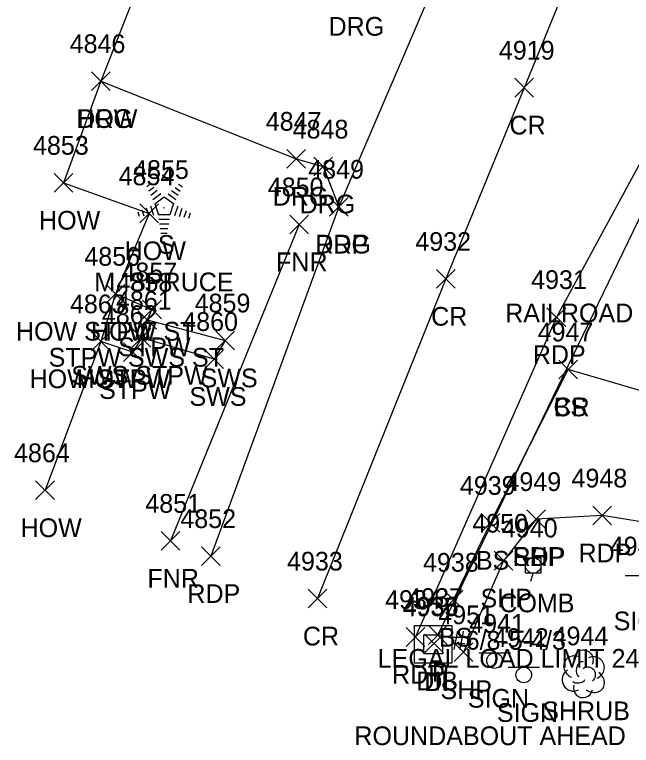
# Model space of a CAD drawing. Extents: x 1653135 to 1655489, y 602711 to 605684.
# Drawn here: x 1653442.7 to 1653508.5, y 604632.5 to 604710.6 of the extents above; entities that cross this region are included whole.
import ezdxf

# ---------------------------------------------------------------- set-up
doc = ezdxf.new("R2010")
doc.units = 0
for name, color, linetype in [('D_A', 7, 'Continuous'), ('D_I', 7, 'Continuous'), ('D_TIC', 7, 'Continuous'), ('DCP', 7, 'Continuous'), ('DS', 7, 'Continuous'), ('L_A', 7, 'Continuous'), ('L_C', 7, 'Continuous'), ('L_I', 7, 'Continuous'), ('L_TIC', 7, 'Continuous'), ('LBC', 7, 'Continuous'), ('LBF', 7, 'Continuous'), ('LELB', 7, 'Continuous'), ('LFNC', 7, 'Continuous'), ('LSH', 7, 'Continuous'), ('LTC', 7, 'Continuous'), ('M_C', 7, 'Continuous'), ('P_A', 7, 'Continuous'), ('P_I', 7, 'Continuous'), ('P_TIC', 7, 'Continuous'), ('PET', 7, 'Continuous'), ('PRC', 7, 'Continuous'), ('PSP', 7, 'Continuous'), ('R_A', 7, 'Continuous'), ('R_I', 7, 'Continuous'), ('R_TIC', 7, 'Continuous'), ('RDG', 7, 'Continuous'), ('RSW', 7, 'Continuous'), ('S_A', 7, 'Continuous'), ('S_C', 7, 'Continuous'), ('S_I', 7, 'Continuous'), ('SSGN', 7, 'Continuous'), ('U_A', 7, 'Continuous'), ('U_C', 7, 'Continuous'), ('U_I', 7, 'Continuous'), ('UP', 7, 'Continuous')]:
    doc.layers.add(name, color=color, linetype=linetype)

msp = doc.modelspace()

# ---------------------------------------------------------------- linework, layer by layer
at = {"layer": 'D_TIC'}
for points in [[(1653486.856, 604643.339), (1653488.856, 604645.339)], [(1653488.856, 604643.339), (1653486.856, 604645.339)], [(1653486.856, 604643.339), (1653488.856, 604645.339)], [(1653488.856, 604643.339), (1653486.856, 604645.339)], [(1653486.449, 604642.424), (1653488.449, 604644.424)], [(1653488.449, 604642.424), (1653486.449, 604644.424)], [(1653486.449, 604642.424), (1653488.449, 604644.424)], [(1653488.449, 604642.424), (1653486.449, 604644.424)]]:
    msp.add_lwpolyline(points, dxfattribs=at)
at = {"layer": 'DCP'}
msp.add_lwpolyline([(1653550.926, 604774.784), (1653487.856, 604644.339)], dxfattribs=at)
at = {"layer": 'DS'}
for p, q in [((1653485.358, 604645.338), (1653489.358, 604645.338)), ((1653485.358, 604641.338), (1653485.358, 604645.338)), ((1653489.358, 604645.338), (1653489.358, 604641.338)), ((1653486.358, 604642.338), (1653486.358, 604644.338)), ((1653486.358, 604644.338), (1653488.358, 604644.338)), ((1653488.358, 604644.338), (1653488.358, 604642.338)), ((1653487.363, 604643.34), (1653487.363, 604643.34)), ((1653487.363, 604643.34), (1653487.363, 604643.34)), ((1653488.358, 604642.338), (1653486.358, 604642.338)), ((1653489.358, 604641.338), (1653485.358, 604641.338))]:
    msp.add_line(p, q, dxfattribs=at)
at = {"layer": 'L_TIC'}
for points in [[(1653450.866, 604702.506), (1653452.866, 604704.506)], [(1653452.866, 604702.506), (1653450.866, 604704.506)], [(1653450.866, 604702.506), (1653452.866, 604704.506)], [(1653452.866, 604702.506), (1653450.866, 604704.506)], [(1653446.898, 604691.645), (1653448.898, 604693.645)], [(1653448.898, 604691.645), (1653446.898, 604693.645)], [(1653446.898, 604691.645), (1653448.898, 604693.645)], [(1653448.898, 604691.645), (1653446.898, 604693.645)], [(1653456.038, 604688.383), (1653458.038, 604690.383)], [(1653458.038, 604688.383), (1653456.038, 604690.383)], [(1653456.038, 604688.383), (1653458.038, 604690.383)], [(1653458.038, 604688.383), (1653456.038, 604690.383)], [(1653472.053, 604687.202), (1653474.053, 604689.202)], [(1653474.053, 604687.202), (1653472.053, 604689.202)], [(1653472.053, 604687.202), (1653474.053, 604689.202)], [(1653474.053, 604687.202), (1653472.053, 604689.202)], [(1653452.437, 604679.785), (1653454.437, 604681.785)], [(1653454.437, 604679.785), (1653452.437, 604681.785)], [(1653452.437, 604679.785), (1653454.437, 604681.785)], [(1653454.437, 604679.785), (1653452.437, 604681.785)], [(1653452.437, 604679.785), (1653454.437, 604681.785)], [(1653454.437, 604679.785), (1653452.437, 604681.785)], [(1653452.437, 604679.785), (1653454.437, 604681.785)], [(1653454.437, 604679.785), (1653452.437, 604681.785)], [(1653456.34, 604678.12), (1653458.34, 604680.12)], [(1653458.34, 604678.12), (1653456.34, 604680.12)], [(1653456.34, 604678.12), (1653458.34, 604680.12)], [(1653458.34, 604678.12), (1653456.34, 604680.12)], [(1653455.818, 604677.007), (1653457.818, 604679.007)], [(1653457.818, 604677.007), (1653455.818, 604679.007)], [(1653455.818, 604677.007), (1653457.818, 604679.007)], [(1653457.818, 604677.007), (1653455.818, 604679.007)], [(1653450.891, 604674.708), (1653452.891, 604676.708)], [(1653452.891, 604674.708), (1653450.891, 604676.708)], [(1653450.891, 604674.708), (1653452.891, 604676.708)], [(1653452.891, 604674.708), (1653450.891, 604676.708)], [(1653450.891, 604674.708), (1653452.891, 604676.708)], [(1653452.891, 604674.708), (1653450.891, 604676.708)], [(1653450.891, 604674.708), (1653452.891, 604676.708)], [(1653452.891, 604674.708), (1653450.891, 604676.708)], [(1653455.235, 604675.075), (1653457.235, 604677.075)], [(1653457.235, 604675.075), (1653455.235, 604677.075)], [(1653455.235, 604675.075), (1653457.235, 604677.075)], [(1653457.235, 604675.075), (1653455.235, 604677.075)], [(1653454.3, 604673.557), (1653456.3, 604675.557)], [(1653456.3, 604673.557), (1653454.3, 604675.557)], [(1653454.3, 604673.557), (1653456.3, 604675.557)], [(1653456.3, 604673.557), (1653454.3, 604675.557)], [(1653500.776, 604671.702), (1653502.776, 604673.702)], [(1653502.776, 604671.702), (1653500.776, 604673.702)], [(1653500.776, 604671.702), (1653502.776, 604673.702)], [(1653502.776, 604671.702), (1653500.776, 604673.702)], [(1653444.92, 604658.798), (1653446.92, 604660.798)], [(1653446.92, 604658.798), (1653444.92, 604660.798)], [(1653444.92, 604658.798), (1653446.92, 604660.798)], [(1653446.92, 604658.798), (1653444.92, 604660.798)], [(1653492.485, 604655.315), (1653494.485, 604657.315)], [(1653494.485, 604655.315), (1653492.485, 604657.315)], [(1653492.485, 604655.315), (1653494.485, 604657.315)], [(1653494.485, 604655.315), (1653492.485, 604657.315)], [(1653458.32, 604653.393), (1653460.32, 604655.393)], [(1653460.32, 604653.393), (1653458.32, 604655.393)], [(1653458.32, 604653.393), (1653460.32, 604655.393)], [(1653460.32, 604653.393), (1653458.32, 604655.393)], [(1653488.539, 604647.099), (1653490.539, 604649.099)], [(1653490.539, 604647.099), (1653488.539, 604649.099)], [(1653488.539, 604647.099), (1653490.539, 604649.099)], [(1653490.539, 604647.099), (1653488.539, 604649.099)]]:
    msp.add_lwpolyline(points, dxfattribs=at)
at = {"layer": 'LBC'}
msp.add_lwpolyline([(1653458.195, 604719.563), (1653451.866, 604703.506), (1653447.898, 604692.645), (1653457.038, 604689.383), (1653453.437, 604680.785), (1653451.891, 604675.708), (1653445.92, 604659.798)], dxfattribs=at)
at = {"layer": 'LBF'}
msp.add_lwpolyline([(1653453.437, 604680.785), (1653457.34, 604679.12), (1653456.818, 604678.007), (1653456.235, 604676.075), (1653455.3, 604674.557), (1653451.891, 604675.708)], dxfattribs=at)
at = {"layer": 'LELB'}
msp.add_lwpolyline([(1653489.539, 604648.099), (1653493.485, 604656.315), (1653501.776, 604672.702)], dxfattribs=at)
at = {"layer": 'LFNC'}
msp.add_lwpolyline([(1653473.053, 604688.202), (1653459.32, 604654.393)], dxfattribs=at)
at = {"layer": 'LSH'}
msp.add_line((1653503.376, 604640.237), (1653503.376, 604640.237), dxfattribs=at)
msp.add_line((1653503.376, 604640.237), (1653503.376, 604640.237), dxfattribs=at)
msp.add_arc((1653503.423, 604641.671), 1.047, 335.52715, 180.95627, dxfattribs=at)
for centre, major_axis, ratio, start_param, end_param in [((1653502.584, 604640.904), (1.21, -0.512), 0.895232, 1.570796, 4.712389), ((1653503.168, 604640.696), (-0.208, -0.792), 0.645439, 3.141593, 6.283185), ((1653504.418, 604640.821), (-1.141, -0.483), 0.949671, 1.570796, 4.712389), ((1653503.876, 604640.071), (-0.5, 0.667), 0.989748, 3.141593, 6.283185), ((1653502.293, 604639.529), (0.584, -1.042), 0.959034, 3.141593, 6.283185), ((1653504.376, 604639.404), (-1.09, 0.792), 0.841452, 1.570796, 4.712389), ((1653502.918, 604639.487), (-0.625, -0.083), 0.423636, 0, 3.141593), ((1653503.376, 604638.737), (0.265, 1.061), 0.942809, 1.570796, 4.712389)]:
    msp.add_ellipse(centre, major_axis=major_axis, ratio=ratio, start_param=start_param, end_param=end_param, dxfattribs=at)
at = {"layer": 'LTC'}
for p, q in [((1653456.785, 604692.268), (1653457.14, 604692.525)), ((1653460.183, 604692.508), (1653460.602, 604692.204)), ((1653456.995, 604691.802), (1653457.524, 604692.186)), ((1653457.204, 604691.336), (1653457.908, 604691.848)), ((1653457.414, 604690.871), (1653458.292, 604691.509)), ((1653459.07, 604691.463), (1653459.88, 604690.874)), ((1653459.441, 604691.811), (1653460.12, 604691.318)), ((1653459.812, 604692.16), (1653460.362, 604691.761)), ((1653457.638, 604690.416), (1653458.65, 604691.15)), ((1653458.65, 604691.15), (1653459.647, 604690.425)), ((1653456.728, 604689.98), (1653457, 604689.145)), ((1653457.184, 604690.196), (1653457.515, 604689.177)), ((1653457.638, 604690.416), (1653458.025, 604689.222)), ((1653459.647, 604690.425), (1653459.256, 604689.222)), ((1653460.085, 604690.154), (1653459.747, 604689.115)), ((1653460.529, 604689.904), (1653460.242, 604689.019)), ((1653455.818, 604689.547), (1653455.97, 604689.079)), ((1653456.273, 604689.764), (1653456.485, 604689.112)), ((1653459.256, 604689.222), (1653458.025, 604689.222)), ((1653460.974, 604689.654), (1653460.737, 604688.924)), ((1653461.418, 604689.404), (1653461.231, 604688.829)), ((1653459.218, 604688.722), (1653458.073, 604688.722)), ((1653459.134, 604688.222), (1653458.145, 604688.222)), ((1653459.05, 604687.722), (1653458.218, 604687.722)), ((1653458.966, 604687.222), (1653458.291, 604687.222))]:
    msp.add_line(p, q, dxfattribs=at)
at = {"layer": 'P_TIC'}
for points in [[(1653496.08, 604701.808), (1653498.08, 604703.808)], [(1653498.08, 604701.808), (1653496.08, 604703.808)], [(1653496.08, 604701.808), (1653498.08, 604703.808)], [(1653498.08, 604701.808), (1653496.08, 604703.808)], [(1653476.29, 604689.088), (1653478.29, 604691.088)], [(1653478.29, 604689.088), (1653476.29, 604691.088)], [(1653476.29, 604689.088), (1653478.29, 604691.088)], [(1653478.29, 604689.088), (1653476.29, 604691.088)], [(1653487.718, 604681.378), (1653489.718, 604683.378)], [(1653489.718, 604681.378), (1653487.718, 604683.378)], [(1653487.718, 604681.378), (1653489.718, 604683.378)], [(1653489.718, 604681.378), (1653487.718, 604683.378)], [(1653499.514, 604677.3), (1653501.514, 604679.3)], [(1653501.514, 604677.3), (1653499.514, 604679.3)], [(1653499.514, 604677.3), (1653501.514, 604679.3)], [(1653501.514, 604677.3), (1653499.514, 604679.3)], [(1653500.776, 604671.702), (1653502.776, 604673.702)], [(1653502.776, 604671.702), (1653500.776, 604673.702)], [(1653500.776, 604671.702), (1653502.776, 604673.702)], [(1653502.776, 604671.702), (1653500.776, 604673.702)], [(1653504.395, 604656.097), (1653506.395, 604658.097)], [(1653506.395, 604656.097), (1653504.395, 604658.097)], [(1653504.395, 604656.097), (1653506.395, 604658.097)], [(1653506.395, 604656.097), (1653504.395, 604658.097)], [(1653497.348, 604655.721), (1653499.348, 604657.721)], [(1653499.348, 604655.721), (1653497.348, 604657.721)], [(1653497.348, 604655.721), (1653499.348, 604657.721)], [(1653499.348, 604655.721), (1653497.348, 604657.721)], [(1653497.348, 604655.721), (1653499.348, 604657.721)], [(1653499.348, 604655.721), (1653497.348, 604657.721)], [(1653497.348, 604655.721), (1653499.348, 604657.721)], [(1653499.348, 604655.721), (1653497.348, 604657.721)], [(1653462.629, 604651.761), (1653464.629, 604653.761)], [(1653464.629, 604651.761), (1653462.629, 604653.761)], [(1653462.629, 604651.761), (1653464.629, 604653.761)], [(1653464.629, 604651.761), (1653462.629, 604653.761)], [(1653493.884, 604651.277), (1653495.884, 604653.277)], [(1653495.884, 604651.277), (1653493.884, 604653.277)], [(1653493.884, 604651.277), (1653495.884, 604653.277)], [(1653495.884, 604651.277), (1653493.884, 604653.277)], [(1653474.021, 604647.225), (1653476.021, 604649.225)], [(1653476.021, 604647.225), (1653474.021, 604649.225)], [(1653474.021, 604647.225), (1653476.021, 604649.225)], [(1653476.021, 604647.225), (1653474.021, 604649.225)], [(1653484.489, 604643.125), (1653486.489, 604645.125)], [(1653486.489, 604643.125), (1653484.489, 604645.125)], [(1653484.489, 604643.125), (1653486.489, 604645.125)], [(1653486.489, 604643.125), (1653484.489, 604645.125)], [(1653489.601, 604641.491), (1653491.601, 604643.491)], [(1653491.601, 604641.491), (1653489.601, 604643.491)], [(1653489.601, 604641.491), (1653491.601, 604643.491)], [(1653491.601, 604641.491), (1653489.601, 604643.491)]]:
    msp.add_lwpolyline(points, dxfattribs=at)
at = {"layer": 'PET'}
for points in [[(1653633.646, 605084.486), (1653621.617, 605050.514), (1653609.161, 605016.811), (1653593.415, 604976.628), (1653581.247, 604945.503), (1653566.997, 604910.296), (1653555.966, 604883.53), (1653545.833, 604858.095), (1653540.542, 604853.303), (1653537.113, 604852.972), (1653527.536, 604814.719), (1653509.397, 604769.005), (1653501.575, 604747.875), (1653488.316, 604715.865), (1653477.29, 604690.088), (1653463.629, 604652.761)], [(1653655.918, 605064.805), (1653642.791, 605030.68), (1653630.635, 604998.758), (1653616.346, 604961.777), (1653606.999, 604938.902), (1653591.982, 604901.991), (1653581.825, 604875.405), (1653576.402, 604861.576), (1653566.832, 604837.99), (1653550.837, 604800.627), (1653535.679, 604761.751), (1653523.656, 604730.259), (1653512.191, 604699.831), (1653500.514, 604678.3), (1653485.489, 604644.125)], [(1653523.002, 604654.237), (1653505.395, 604657.097), (1653498.348, 604656.721)]]:
    msp.add_lwpolyline(points, dxfattribs=at)
at = {"layer": 'PRC'}
for points in [[(1653642.794, 605070.13), (1653630.687, 605038.22), (1653617.604, 605002.899), (1653603.985, 604967.155), (1653594.728, 604943.347), (1653580.105, 604906.755), (1653569.49, 604880.56), (1653554.212, 604842.781), (1653538.782, 604804.489), (1653523.366, 604766.647), (1653509.987, 604734.396), (1653497.08, 604702.808), (1653488.718, 604682.378), (1653475.021, 604648.225)], [(1653524.893, 604665.941), (1653501.776, 604672.702)]]:
    msp.add_lwpolyline(points, dxfattribs=at)
at = {"layer": 'PSP'}
msp.add_lwpolyline([(1653498.348, 604656.721), (1653494.884, 604652.277), (1653490.601, 604642.491)], dxfattribs=at)
at = {"layer": 'R_TIC'}
for points in [[(1653450.866, 604702.506), (1653452.866, 604704.506)], [(1653452.866, 604702.506), (1653450.866, 604704.506)], [(1653450.866, 604702.506), (1653452.866, 604704.506)], [(1653452.866, 604702.506), (1653450.866, 604704.506)], [(1653471.745, 604694.21), (1653473.745, 604696.21)], [(1653473.745, 604694.21), (1653471.745, 604696.21)], [(1653471.745, 604694.21), (1653473.745, 604696.21)], [(1653473.745, 604694.21), (1653471.745, 604696.21)], [(1653474.623, 604693.377), (1653476.623, 604695.377)], [(1653476.623, 604693.377), (1653474.623, 604695.377)], [(1653474.623, 604693.377), (1653476.623, 604695.377)], [(1653476.623, 604693.377), (1653474.623, 604695.377)], [(1653476.29, 604689.088), (1653478.29, 604691.088)], [(1653478.29, 604689.088), (1653476.29, 604691.088)], [(1653476.29, 604689.088), (1653478.29, 604691.088)], [(1653478.29, 604689.088), (1653476.29, 604691.088)], [(1653455.818, 604677.007), (1653457.818, 604679.007)], [(1653457.818, 604677.007), (1653455.818, 604679.007)], [(1653455.818, 604677.007), (1653457.818, 604679.007)], [(1653457.818, 604677.007), (1653455.818, 604679.007)], [(1653455.235, 604675.075), (1653457.235, 604677.075)], [(1653457.235, 604675.075), (1653455.235, 604677.075)], [(1653455.235, 604675.075), (1653457.235, 604677.075)], [(1653457.235, 604675.075), (1653455.235, 604677.075)], [(1653464.164, 604674.801), (1653466.164, 604676.801)], [(1653466.164, 604674.801), (1653464.164, 604676.801)], [(1653464.164, 604674.801), (1653466.164, 604676.801)], [(1653466.164, 604674.801), (1653464.164, 604676.801)], [(1653462.971, 604672.819), (1653464.971, 604674.819)], [(1653464.971, 604672.819), (1653462.971, 604674.819)], [(1653462.971, 604672.819), (1653464.971, 604674.819)], [(1653464.971, 604672.819), (1653462.971, 604674.819)]]:
    msp.add_lwpolyline(points, dxfattribs=at)
at = {"layer": 'RDG'}
msp.add_lwpolyline([(1653451.866, 604703.506), (1653472.745, 604695.21), (1653475.623, 604694.377), (1653477.29, 604690.088)], dxfattribs=at)
at = {"layer": 'RSW'}
msp.add_lwpolyline([(1653456.818, 604678.007), (1653465.164, 604675.801), (1653463.971, 604673.819), (1653456.235, 604676.075)], dxfattribs=at)
at = {"layer": 'SSGN'}
for p, q in [((1653507.85, 604650.695), (1653511.183, 604650.695)), ((1653492.278, 604642.427), (1653495.611, 604642.427)), ((1653493.925, 604641.594), (1653493.925, 604641.594)), ((1653495.383, 604640.906), (1653498.716, 604640.906)), ((1653497.029, 604640.073), (1653497.029, 604640.073))]:
    msp.add_line(p, q, dxfattribs=at)
for centre in [(1653493.925, 604641.594), (1653497.029, 604640.073)]:
    msp.add_circle(centre, 0.833, dxfattribs=at)
at = {"layer": 'UP'}
for p, q in [((1653498.293, 604653.431), (1653498.043, 604652.597)), ((1653497.209, 604650.931), (1653497.209, 604652.597)), ((1653497.209, 604652.597), (1653498.876, 604652.597)), ((1653498.876, 604652.597), (1653498.876, 604650.931)), ((1653498.043, 604651.764), (1653498.043, 604651.764)), ((1653498.876, 604650.931), (1653497.209, 604650.931)), ((1653497.793, 604650.097), (1653498.043, 604650.931))]:
    msp.add_line(p, q, dxfattribs=at)
msp.add_circle((1653498.043, 604651.764), 0.833, dxfattribs=at)

# ---------------------------------------------------------------- texts
at = {"layer": 'D_A'}
for s, p in [('P', (1653487.234, 604639.339)), ('P', (1653487.234, 604639.339)), ('DIB', (1653485.552, 604638.424)), ('DIB', (1653485.552, 604638.424)), ('DI', (1653486.418, 604638.34))]:
    msp.add_text(s, height=2, dxfattribs=at).set_placement(p)
at = {"layer": 'D_I'}
for s, p in [('4937', (1653484.596, 604647.339)), ('4937', (1653484.596, 604647.339)), ('4935', (1653484.103, 604646.34)), ('4936', (1653484.134, 604646.424)), ('4936', (1653484.134, 604646.424))]:
    msp.add_text(s, height=2, dxfattribs=at).set_placement(p)
at = {"layer": 'L_A'}
for s, p in [('HOW', (1653449.252, 604698.506)), ('HOW', (1653449.252, 604698.506)), ('HOW', (1653445.284, 604687.645)), ('HOW', (1653445.284, 604687.645)), ('S', (1653457.976, 604685.06)), ('HOW', (1653454.424, 604684.383)), ('HOW', (1653454.424, 604684.383)), ('FNR', (1653470.589, 604683.202)), ('FNR', (1653470.589, 604683.202)), ('HOW STPW ST', (1653442.816, 604675.785)), ('HOW STPW ST', (1653442.816, 604675.785)), ('HOW', (1653450.823, 604675.785)), ('HOW', (1653450.823, 604675.785)), ('STPW', (1653453.733, 604674.12)), ('STPW', (1653453.733, 604674.12)), ('STPW SWS ST', (1653446.306, 604673.007)), ('STPW SWS ST', (1653446.306, 604673.007)), ('HOW STPW', (1653444.269, 604670.708)), ('HOW STPW', (1653444.269, 604670.708)), ('SWS STPW', (1653448.723, 604671.075)), ('SWS STPW', (1653448.723, 604671.075)), ('HOW', (1653449.277, 604670.708)), ('HOW', (1653449.277, 604670.708)), ('STPW', (1653451.694, 604669.557)), ('STPW', (1653451.694, 604669.557)), ('BS', (1653500.217, 604667.702)), ('BS', (1653500.217, 604667.702)), ('HOW', (1653443.306, 604654.798)), ('HOW', (1653443.306, 604654.798)), ('BS', (1653491.926, 604651.315)), ('BS', (1653491.926, 604651.315)), ('FNR', (1653456.856, 604649.393)), ('FNR', (1653456.856, 604649.393)), ('BS', (1653487.98, 604643.099)), ('BS', (1653487.98, 604643.099)), ('SHRUB', (1653499.006, 604635.237))]:
    msp.add_text(s, height=2, dxfattribs=at).set_placement(p)
at = {"layer": 'L_C'}
msp.add_text('M. SPRUCE', height=2, dxfattribs=at).set_placement((1653451.188, 604681.06))
at = {"layer": 'L_I'}
for s, p in [('4846', (1653448.551, 604706.506)), ('4846', (1653448.551, 604706.506)), ('4853', (1653444.638, 604695.645)), ('4853', (1653444.638, 604695.645)), ('4855', (1653455.33, 604693.06)), ('4854', (1653453.778, 604692.383)), ('4854', (1653453.778, 604692.383)), ('4850', (1653469.707, 604691.202)), ('4850', (1653469.707, 604691.202)), ('4856', (1653450.123, 604683.785)), ('4856', (1653450.123, 604683.785)), ('4856', (1653450.123, 604683.785)), ('4856', (1653450.123, 604683.785)), ('4857', (1653454.08, 604682.12)), ('4857', (1653454.08, 604682.12)), ('4858', (1653453.558, 604681.007)), ('4858', (1653453.558, 604681.007)), ('4863', (1653448.584, 604678.708)), ('4863', (1653448.584, 604678.708)), ('4863', (1653448.584, 604678.708)), ('4863', (1653448.584, 604678.708)), ('4861', (1653453.495, 604679.075)), ('4861', (1653453.495, 604679.075)), ('4862', (1653451.993, 604677.557)), ('4862', (1653451.993, 604677.557)), ('4947', (1653498.516, 604675.702)), ('4947', (1653498.516, 604675.702)), ('4864', (1653442.613, 604662.798)), ('4864', (1653442.613, 604662.798)), ('4939', (1653490.217, 604659.315)), ('4939', (1653490.217, 604659.315)), ('4851', (1653456.628, 604657.393)), ('4851', (1653456.628, 604657.393)), ('4938', (1653486.279, 604651.099)), ('4938', (1653486.279, 604651.099)), ('4944', (1653500.116, 604643.237))]:
    msp.add_text(s, height=2, dxfattribs=at).set_placement(p)
at = {"layer": 'LTC'}
msp.add_text('.', height=1.037, rotation=270, dxfattribs=at).set_placement((1653458.533, 604690.164))
at = {"layer": 'M_C'}
msp.add_text('RAILROAD SPIKE IN PAVEMENT', height=2, dxfattribs=at).set_placement((1653495.054, 604677.741))
at = {"layer": 'P_A'}
for s, p in [('CR', (1653495.513, 604697.808)), ('CR', (1653495.513, 604697.808)), ('RDP', (1653474.779, 604685.088)), ('RDP', (1653474.779, 604685.088)), ('CR', (1653487.151, 604677.378)), ('CR', (1653487.151, 604677.378)), ('RDP', (1653498.002, 604673.3)), ('RDP', (1653498.002, 604673.3)), ('CR', (1653500.209, 604667.702)), ('CR', (1653500.209, 604667.702)), ('RDP', (1653502.883, 604652.097)), ('RDP', (1653502.883, 604652.097)), ('SHP', (1653495.884, 604651.721)), ('SHP', (1653495.884, 604651.721)), ('RDP', (1653495.836, 604651.721)), ('RDP', (1653495.836, 604651.721)), ('RDP', (1653461.118, 604647.761)), ('RDP', (1653461.118, 604647.761)), ('SHP', (1653492.42, 604647.277)), ('SHP', (1653492.42, 604647.277)), ('CR', (1653473.454, 604643.225)), ('CR', (1653473.454, 604643.225)), ('RDP', (1653482.977, 604639.125)), ('RDP', (1653482.977, 604639.125)), ('SHP', (1653488.137, 604637.491)), ('SHP', (1653488.137, 604637.491))]:
    msp.add_text(s, height=2, dxfattribs=at).set_placement(p)
at = {"layer": 'P_I'}
for s, p in [('4919', (1653494.38, 604705.808)), ('4919', (1653494.38, 604705.808)), ('4849', (1653474.023, 604693.088)), ('4849', (1653474.023, 604693.088)), ('4932', (1653485.458, 604685.378)), ('4932', (1653485.458, 604685.378)), ('4931', (1653497.822, 604681.3)), ('4931', (1653497.822, 604681.3)), ('4947', (1653498.516, 604675.702)), ('4947', (1653498.516, 604675.702)), ('4948', (1653502.135, 604660.097)), ('4948', (1653502.135, 604660.097)), ('4949', (1653495.081, 604659.721)), ('4949', (1653495.081, 604659.721)), ('4949', (1653495.081, 604659.721)), ('4949', (1653495.081, 604659.721)), ('4852', (1653460.37, 604655.761)), ('4852', (1653460.37, 604655.761)), ('4950', (1653491.538, 604655.277)), ('4950', (1653491.538, 604655.277)), ('4933', (1653471.761, 604651.225)), ('4933', (1653471.761, 604651.225)), ('4934', (1653482.229, 604647.125)), ('4934', (1653482.229, 604647.125)), ('4951', (1653487.909, 604645.491)), ('4951', (1653487.909, 604645.491))]:
    msp.add_text(s, height=2, dxfattribs=at).set_placement(p)
at = {"layer": 'R_A'}
for s, p in [('DRG', (1653476.191, 604708.358)), ('DRG', (1653476.191, 604708.358)), ('DRG', (1653449.354, 604698.506)), ('DRG', (1653449.354, 604698.506)), ('DRG', (1653470.234, 604690.21)), ('DRG', (1653470.234, 604690.21)), ('DRG', (1653473.111, 604689.377)), ('DRG', (1653473.111, 604689.377)), ('DRG', (1653474.779, 604685.088)), ('DRG', (1653474.779, 604685.088)), ('STPW SWS ST', (1653446.306, 604673.007)), ('STPW SWS ST', (1653446.306, 604673.007)), ('SWS STPW', (1653448.723, 604671.075)), ('SWS STPW', (1653448.723, 604671.075)), ('SWS', (1653462.534, 604670.801)), ('SWS', (1653462.534, 604670.801)), ('SWS', (1653461.341, 604668.819)), ('SWS', (1653461.341, 604668.819))]:
    msp.add_text(s, height=2, dxfattribs=at).set_placement(p)
at = {"layer": 'R_I'}
for s, p in [('4846', (1653448.551, 604706.506)), ('4846', (1653448.551, 604706.506)), ('4847', (1653469.486, 604698.21)), ('4847', (1653469.486, 604698.21)), ('4848', (1653472.363, 604697.377)), ('4848', (1653472.363, 604697.377)), ('4849', (1653474.023, 604693.088)), ('4849', (1653474.023, 604693.088)), ('4858', (1653453.558, 604681.007)), ('4858', (1653453.558, 604681.007)), ('4861', (1653453.495, 604679.075)), ('4861', (1653453.495, 604679.075)), ('4859', (1653461.897, 604678.801)), ('4859', (1653461.897, 604678.801)), ('4860', (1653460.577, 604676.819)), ('4860', (1653460.577, 604676.819))]:
    msp.add_text(s, height=2, dxfattribs=at).set_placement(p)
at = {"layer": 'S_A'}
for p in [(1653506.635, 604644.842), (1653491.063, 604636.574), (1653494.168, 604635.053)]:
    msp.add_text('SIGN', height=2, dxfattribs=at).set_placement(p)
at = {"layer": 'S_C'}
for s, p in [('LEGAL LOAD LIMIT 24000 LBS & NO', (1653481.439, 604640.842)), ('ROUNDABOUT AHEAD', (1653478.953, 604632.574))]:
    msp.add_text(s, height=2, dxfattribs=at).set_placement(p)
at = {"layer": 'S_I'}
for s, p in [('4943', (1653506.218, 604652.842)), ('4941', (1653491.212, 604644.574)), ('4942', (1653493.75, 604643.053))]:
    msp.add_text(s, height=2, dxfattribs=at).set_placement(p)
at = {"layer": 'U_A'}
msp.add_text('COMB', height=2, dxfattribs=at).set_placement((1653494.428, 604646.764))
at = {"layer": 'U_C'}
msp.add_text('#6/8-5-4/3', height=2, dxfattribs=at).set_placement((1653489.35, 604642.764))
at = {"layer": 'U_I'}
msp.add_text('4940', height=2, dxfattribs=at).set_placement((1653494.696, 604654.764))

doc.saveas('drawing.dxf')
